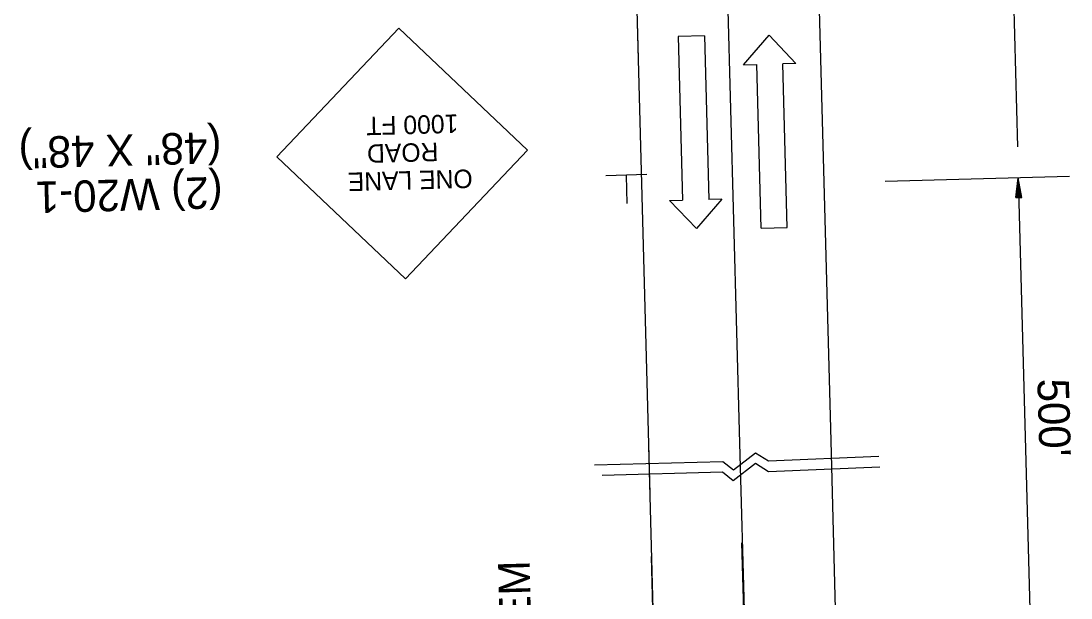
# Model space of a CAD drawing. Extents: x 1929624 to 1932070, y 596315 to 605533.
# Drawn here: x 1931216.1 to 1931416.4, y 596871 to 596981 of the extents above; entities that cross this region are included whole.
import ezdxf

# ---------------------------------------------------------------- set-up
doc = ezdxf.new("R2010")
doc.units = 0
doc.layers.add('Default', color=7, linetype='Continuous')
doc.layers.add('R_MOT', color=7, linetype='Continuous')

msp = doc.modelspace()

# ---------------------------------------------------------------- linework, layer by layer
at = {"layer": 'Default'}
for p, q in [((1931331.85, 597048.08), (1931333.84, 596973.76)), ((1931404.8, 597009.18), (1931406.2, 596957.01)), ((1931333.5, 596986.58), (1931336.07, 596890.83)), ((1931350.88, 596987.04), (1931353.2, 596900.47)), ((1931368.25, 596987.51), (1931370.58, 596900.94)), ((1931264.95, 596955.11), (1931288.2, 596979.62)), ((1931288.2, 596979.62), (1931312.74, 596956.39)), ((1931264.95, 596955.11), (1931289.49, 596931.85)), ((1931289.49, 596931.85), (1931312.74, 596956.39)), ((1931327.68, 596951.55), (1931335.5, 596951.76)), ((1931331.57, 596951.53), (1931331.71, 596946.2)), ((1931416.15, 596951.36), (1931380.95, 596950.41)), ((1931405.9, 596947.33), (1931406.36, 596951.09)), ((1931406, 596947.33), (1931406.38, 596950.47)), ((1931406.36, 596951.09), (1931408.98, 596853.64)), ((1931407.03, 596947.36), (1931406.36, 596951.09)), ((1931406.93, 596947.36), (1931406.38, 596950.47)), ((1931406.09, 596947.34), (1931406.4, 596949.82)), ((1931406.18, 596947.34), (1931406.41, 596949.2)), ((1931406.28, 596947.34), (1931406.43, 596948.56)), ((1931406.84, 596947.36), (1931406.4, 596949.82)), ((1931406.74, 596947.35), (1931406.41, 596949.2)), ((1931406.65, 596947.35), (1931406.43, 596948.56)), ((1931405.9, 596947.33), (1931407.03, 596947.36)), ((1931406.38, 596947.34), (1931406.45, 596947.94)), ((1931406.55, 596947.35), (1931406.45, 596947.94)), ((1931353.2, 596900.47), (1931357.49, 596740.61)), ((1931370.58, 596900.94), (1931374.87, 596741.07)), ((1931335.82, 596900), (1931340.11, 596740.14)), ((1931355.29, 596820.56), (1931353.65, 596881.51)), ((1931336.33, 596878.87), (1931337.95, 596818.64))]:
    msp.add_line(p, q, dxfattribs=at)
for points in [[(1931379.74, 596897.94), (1931358.72, 596897.05), (1931356.26, 596898.61), (1931352.02, 596895.33), (1931349.98, 596896.94), (1931325.53, 596896.29)], [(1931379.98, 596895.95), (1931358.69, 596895.05), (1931356.23, 596896.61), (1931351.99, 596893.33), (1931349.95, 596894.94), (1931326.99, 596894.33)]]:
    msp.add_lwpolyline(points, dxfattribs=at)
at = {"layer": 'R_MOT'}
for p, q in [((1931346.48, 596978.19), (1931341.49, 596978.06)), ((1931341.49, 596978.06), (1931342.32, 596946.85)), ((1931346.48, 596978.19), (1931347.32, 596946.98)), ((1931353.97, 596972.65), (1931358.82, 596978.27)), ((1931358.82, 596978.27), (1931363.96, 596972.92)), ((1931353.97, 596972.65), (1931356.47, 596972.72)), ((1931357.3, 596941.5), (1931356.47, 596972.72)), ((1931363.96, 596972.92), (1931361.46, 596972.85)), ((1931362.3, 596941.64), (1931361.46, 596972.85)), ((1931339.82, 596946.78), (1931342.32, 596946.85)), ((1931344.97, 596941.43), (1931339.82, 596946.78)), ((1931349.82, 596947.05), (1931344.97, 596941.43)), ((1931349.82, 596947.05), (1931347.32, 596946.98)), ((1931357.3, 596941.5), (1931362.3, 596941.64))]:
    msp.add_line(p, q, dxfattribs=at)

# ---------------------------------------------------------------- texts
at = {"layer": 'Default'}
for s, height, rotation, p in [('1000 FT', 3.522, 181.5383, (1931299.5, 596963.2)), ('(48" X 48")', 6, 181.5377, (1931254.3, 596959.87)), ('ROAD', 3.52, 181.5377, (1931295.7, 596957.81)), ('(2) W20-1', 6, 181.5377, (1931254.53, 596951.31)), ('ONE LANE', 3.521, 181.5381, (1931302.23, 596952.7)), ("500'", 6, 271.5377, (1931410, 596912.74)), ('PORTABLE TRAFFIC SIGNAL SYSTEM', 6, 91.5377, (1931317.03, 596732.48))]:
    msp.add_text(s, height=height, rotation=rotation, dxfattribs=at).set_placement(p)

doc.saveas('drawing.dxf')
